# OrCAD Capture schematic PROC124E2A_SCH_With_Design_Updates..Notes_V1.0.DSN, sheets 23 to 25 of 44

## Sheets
23 21. BRD ID EEPROM &TEMP SENSORS: size C; title: BOARD ID EEPROM & TEMPERATURE SENSORS
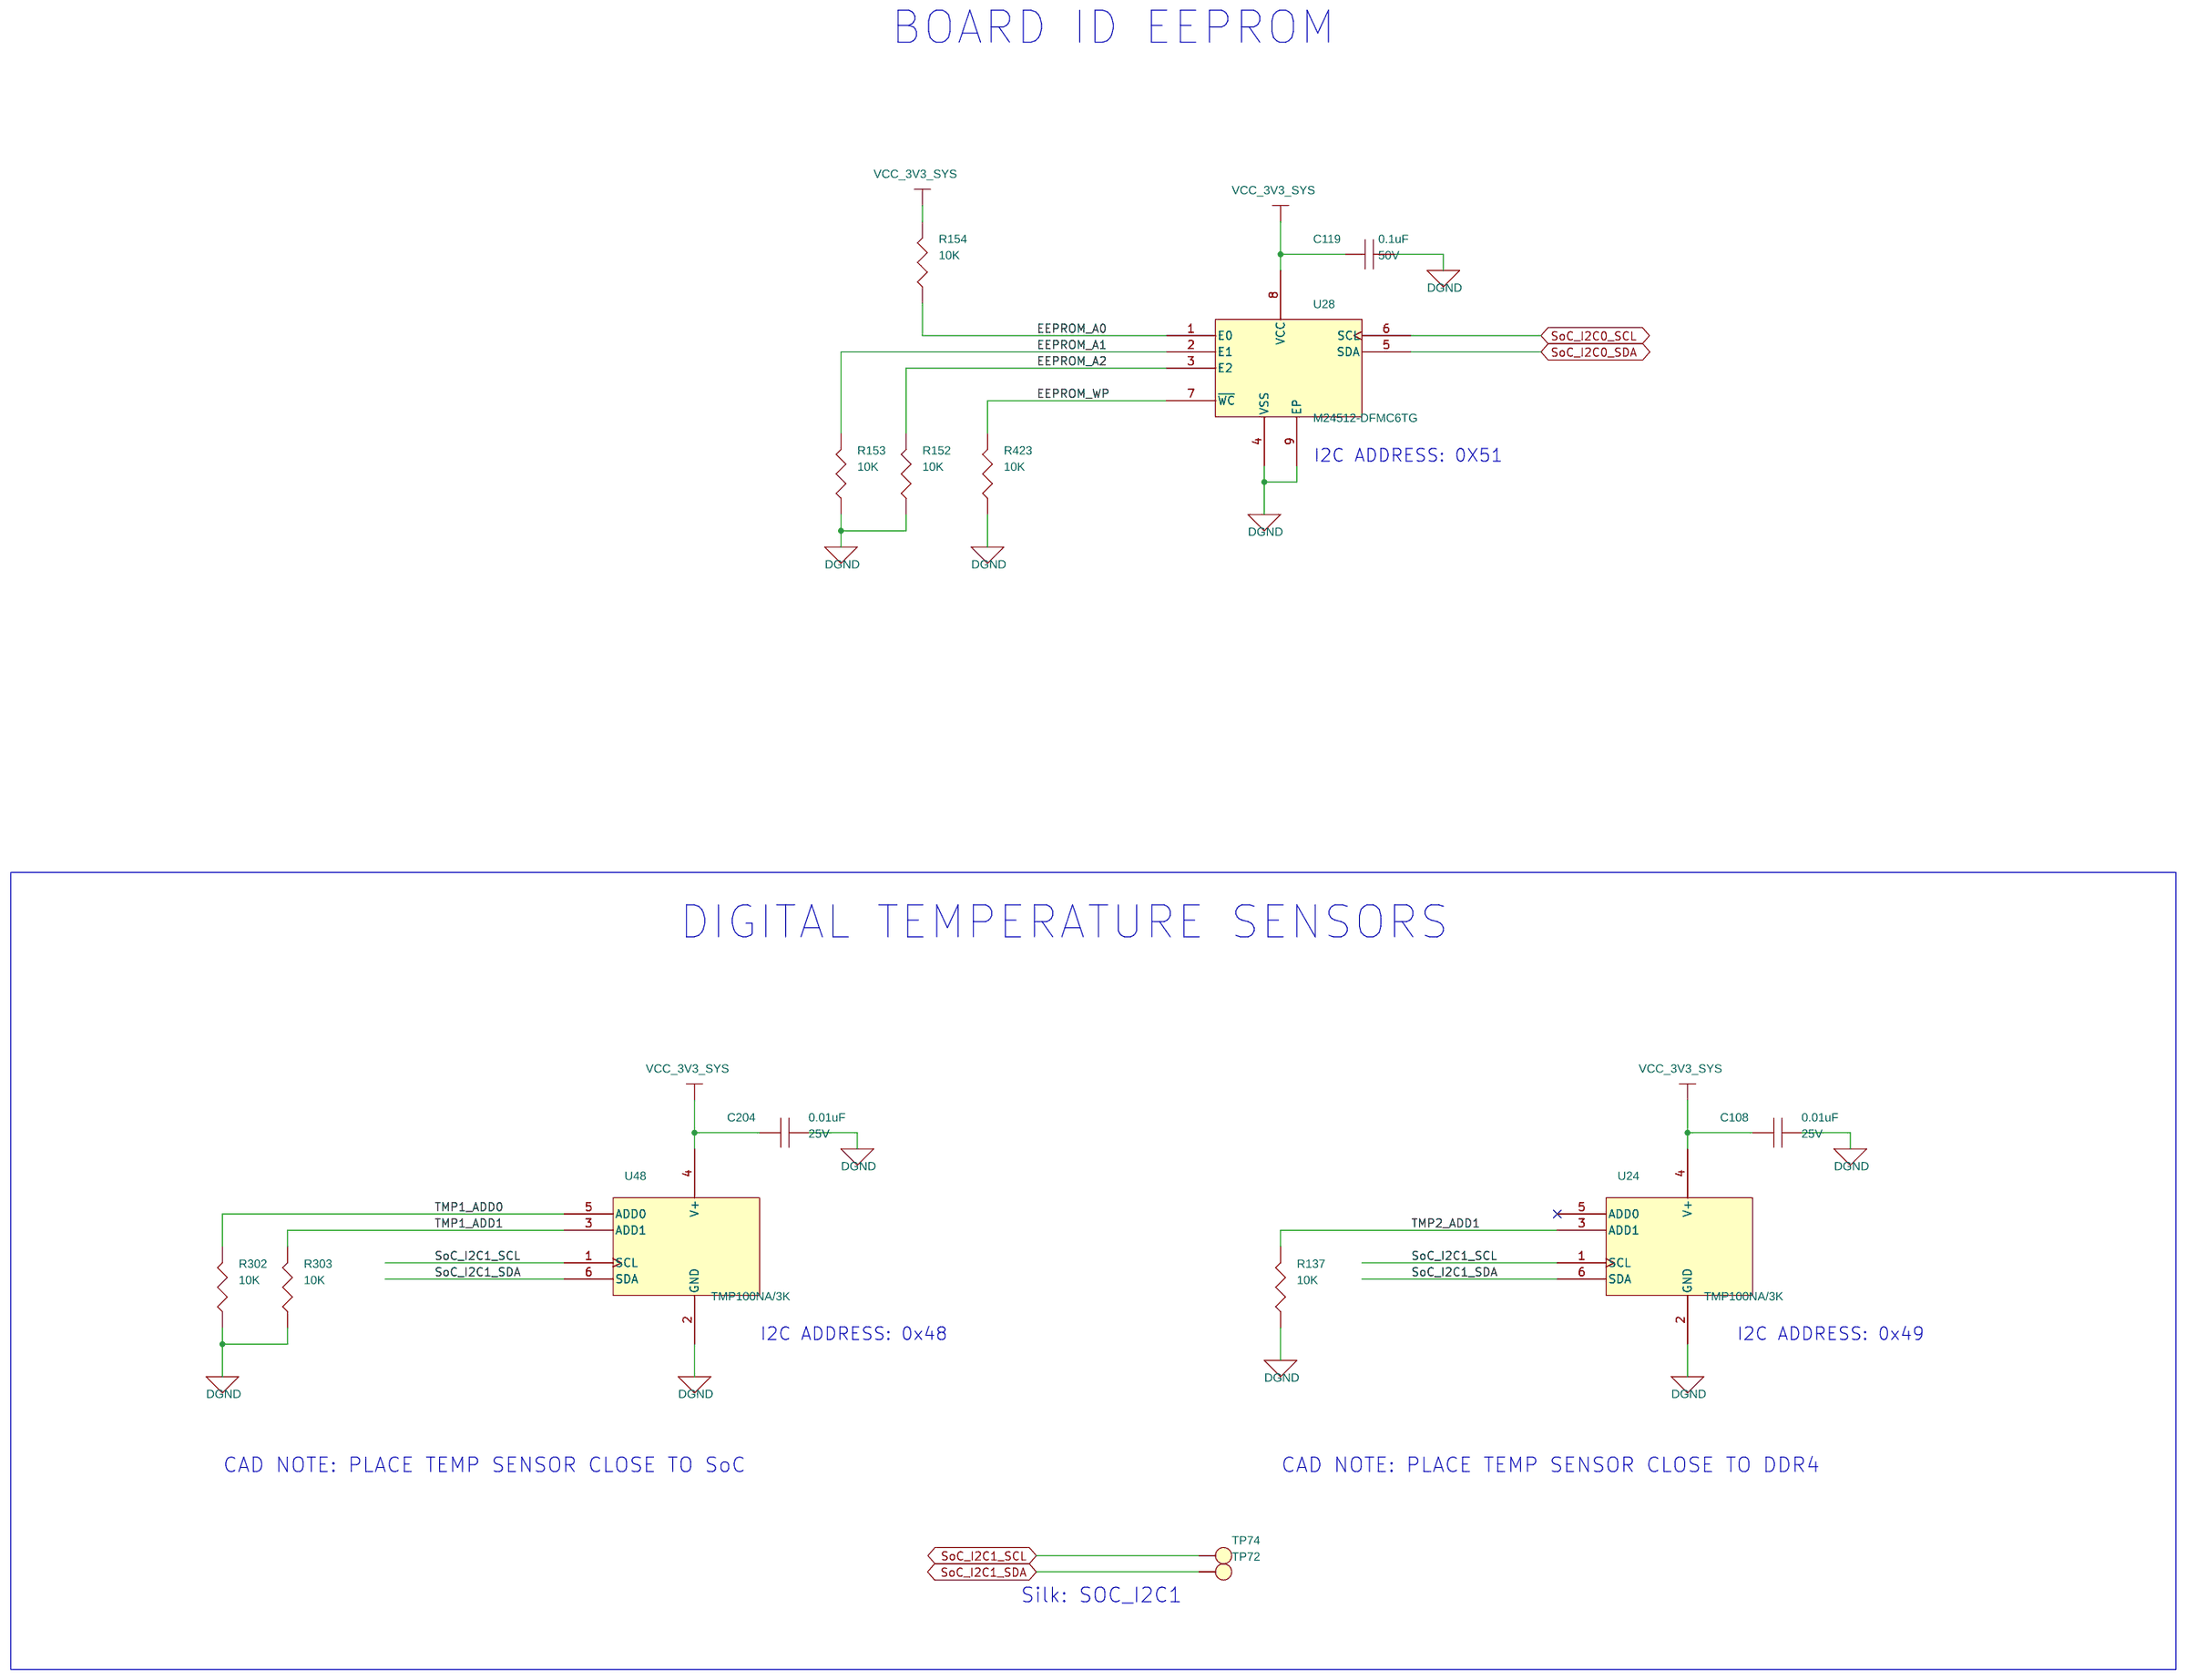
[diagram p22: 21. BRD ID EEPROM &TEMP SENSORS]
24 22. CPSW RGMII_1 ETHERNET PHY: size C
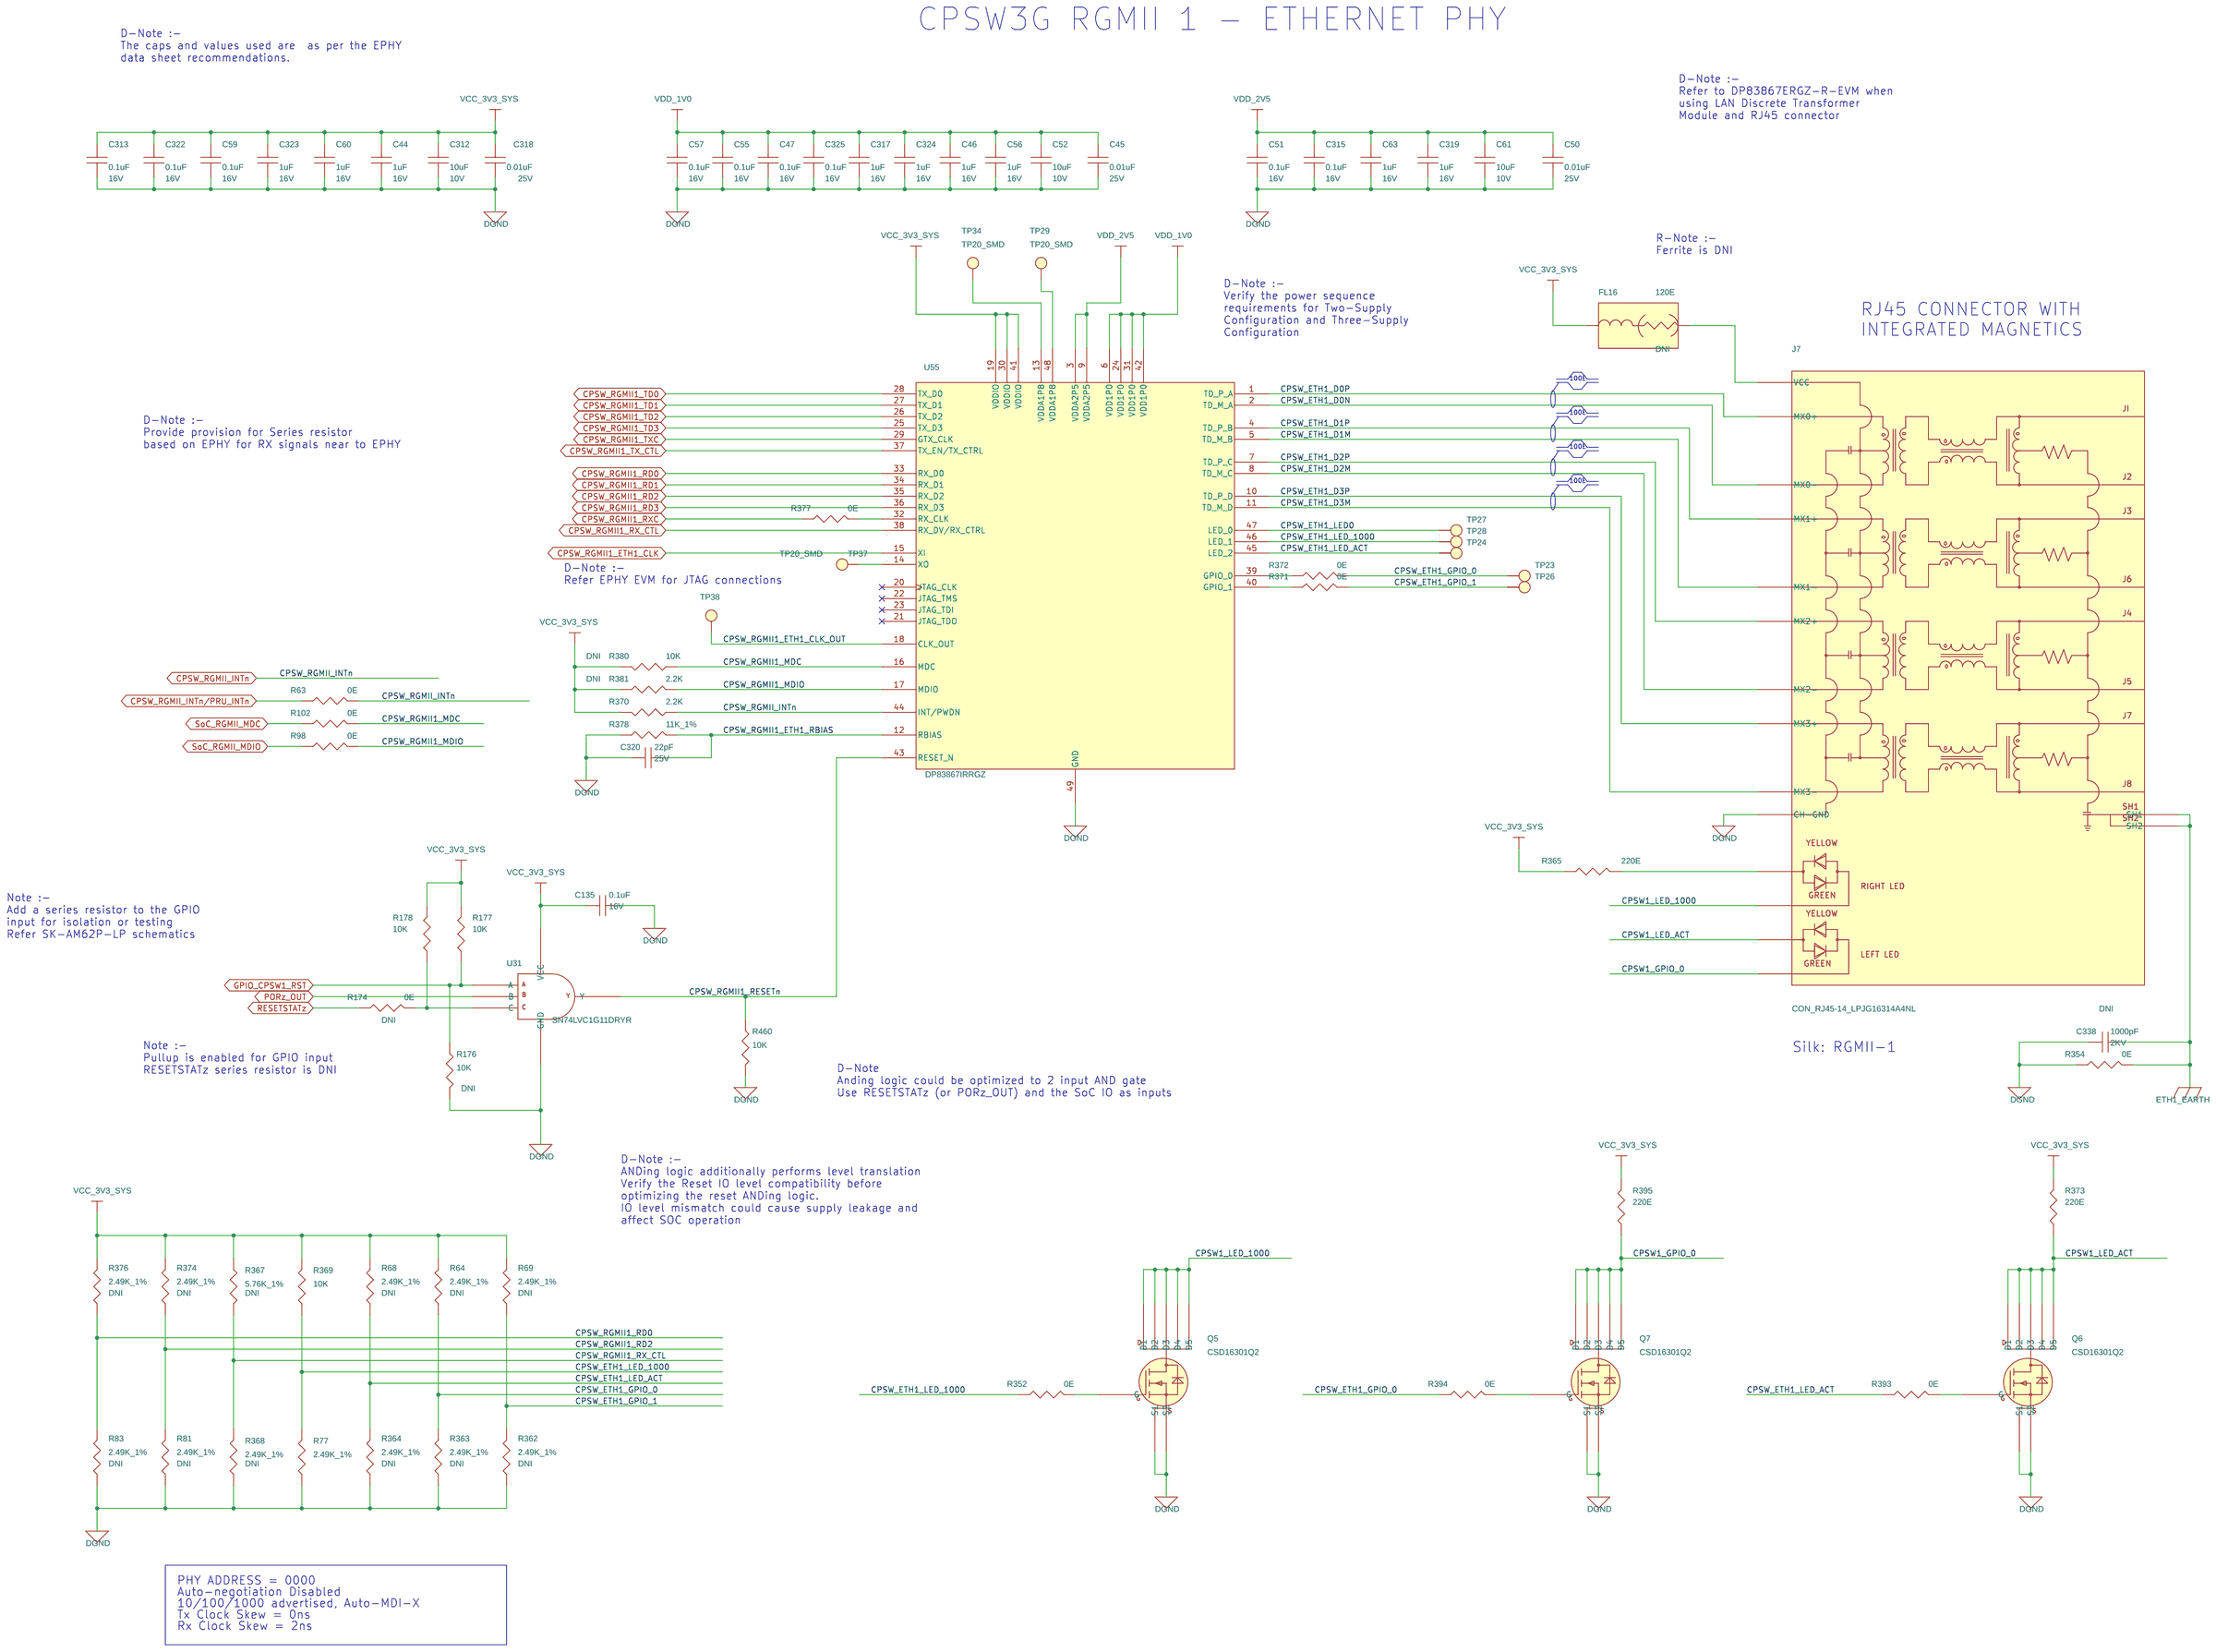
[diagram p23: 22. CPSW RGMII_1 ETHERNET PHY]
25 24. PHY CLK & LED DRIVER: size C; title: ETHERNET PHY CLOCK BUFFER & LED DRIVER
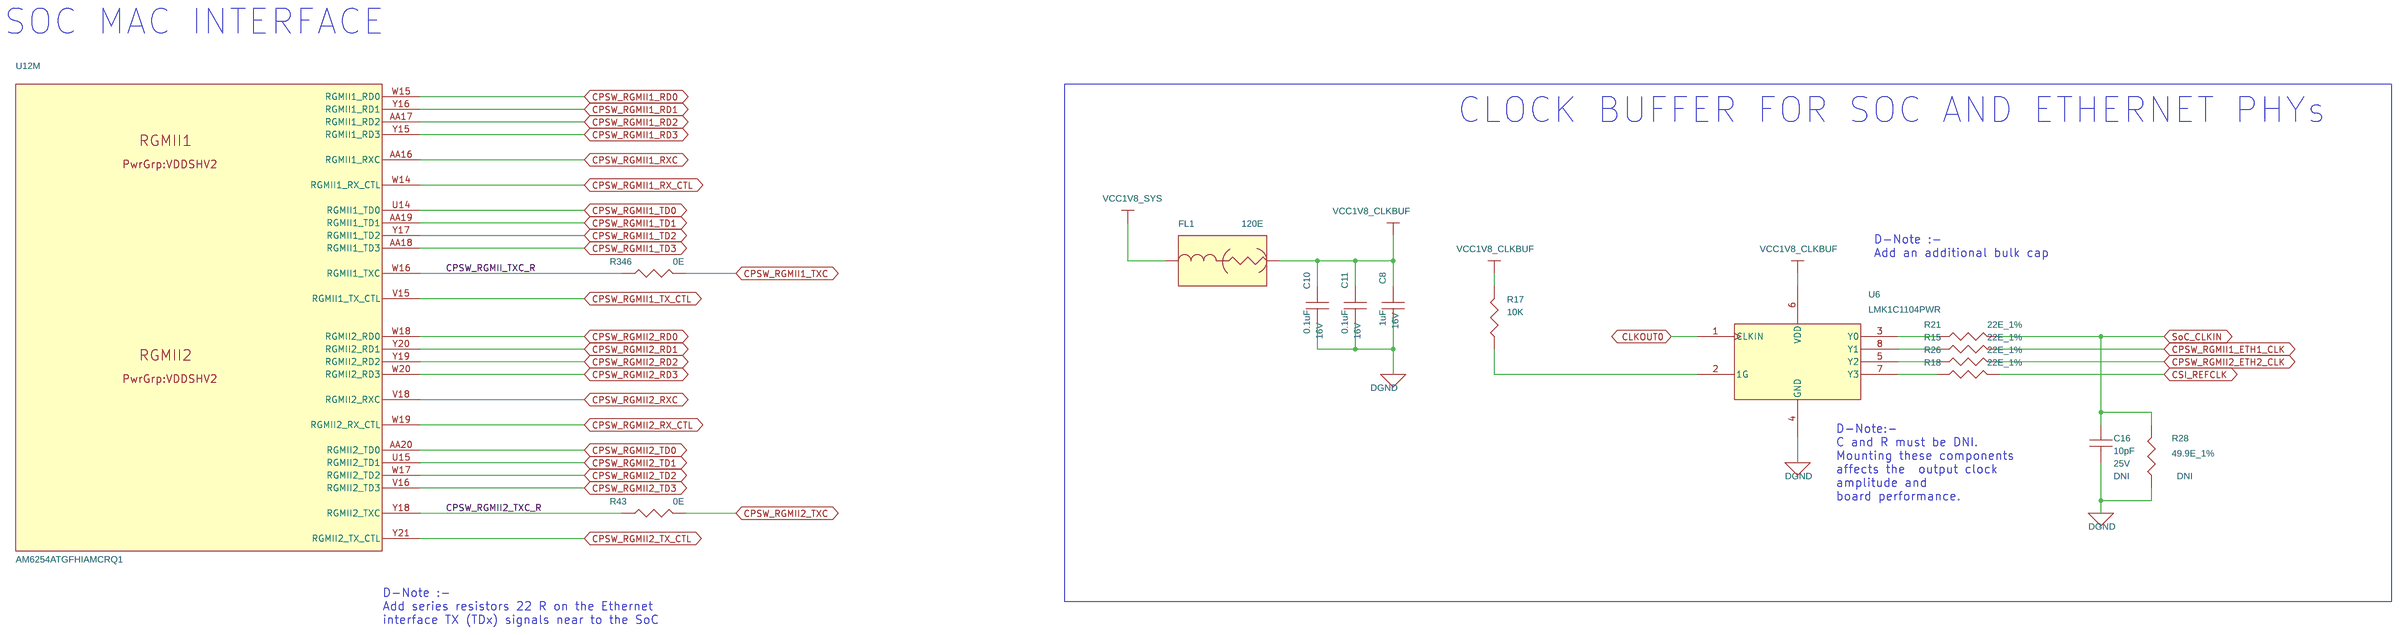
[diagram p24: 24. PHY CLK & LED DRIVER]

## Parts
sheet 15. SOC POWER CAPS
U12  AM6254ATGFHIAMCRQ1  [FCBGA441_31-49_680X680_2-6]  (sections A,B,C,D,E,F,G,H,I,J,K,L,M,N,O,P,Q,R)
sheet 21. BRD ID EEPROM &TEMP SENSORS
C108  0.01uF  [CAP0201_0-5]
C119  0.1uF  [CAP0402_0-75]
C204  0.01uF  [CAP0201_0-5]
R137  10K  [RES0201_0-5]
R152  10K  [RES0201_0-5]
R153  10K  [RES0201_0-5]
R154  10K  [RES0201_0-5]
R302  10K  [RES0201_0-5]
R303  10K  [RES0201_0-5]
R423  10K  [RES0201_0-5]
TP72  TP20_SMD  [TP20_SMD]
TP74  TP20_SMD  [TP20_SMD]
U24  TMP100NA/3K  [SOT23-6_1-5]
U28  M24512-DFMC6TG  [UFDFPN8_M24512_120X80_0-6]
U48  TMP100NA/3K  [SOT23-6_1-5]
sheet 22. CPSW RGMII_1 ETHERNET PHY
C44  1uF  [CAP0201_0-5]
C45  0.01uF  [CAP0201_0-5]
C46  1uF  [CAP0201_0-5]
C47  0.1uF  [CAP0201_0-5]
C50  0.01uF  [CAP0201_0-5]
C51  0.1uF  [CAP0201_0-5]
C52  10uF  [CAP0402_0-75]
C55  0.1uF  [CAP0201_0-5]
C56  1uF  [CAP0201_0-5]
C57  0.1uF  [CAP0201_0-5]
C59  0.1uF  [CAP0201_0-5]
C60  1uF  [CAP0201_0-5]
C61  10uF  [CAP0402_0-75]
C63  1uF  [CAP0201_0-5]
C135  0.1uF  [CAP0201_0-5]
C312  10uF  [CAP0402_0-75]
C313  0.1uF  [CAP0201_0-5]
C315  0.1uF  [CAP0201_0-5]
C317  1uF  [CAP0201_0-5]
C318  0.01uF  [CAP0201_0-5]
C319  1uF  [CAP0201_0-5]
C320  22pF  [CAP0201_0-5]
C322  0.1uF  [CAP0201_0-5]
C323  1uF  [CAP0201_0-5]
C324  1uF  [CAP0201_0-5]
C325  0.1uF  [CAP0201_0-5]
C338  1000pF  [CAP1206_1-75]
FL16  120E  [EMIFIL_BLM15A_0402_0-6]
J7  CON_RJ45-14_LPJG16314A4NL  [CON_RJ45-14_LPJG16314A4NL_S_R_T_13-6]
Q5  CSD16301Q2  [WSON6_CSD13202Q2_80X80_0-8]
Q6  CSD16301Q2  [WSON6_CSD13202Q2_80X80_0-8]
Q7  CSD16301Q2  [WSON6_CSD13202Q2_80X80_0-8]
R63  0E  [RES0402_0-5]
R64  2.49K_1%  [RES0402_0-5]
R68  2.49K_1%  [RES0402_0-5]
R69  2.49K_1%  [RES0402_0-5]
R77  2.49K_1%  [RES0402_0-5]
R81  2.49K_1%  [RES0402_0-5]
R83  2.49K_1%  [RES0402_0-5]
R98  0E  [RES0402_0-5]
R102  0E  [RES0402_0-5]
R174  0E  [RES0201_0-5]
R176  10K  [RES0201_0-5]
R177  10K  [RES0201_0-5]
R178  10K  [RES0201_0-5]
R352  0E  [RES0201_0-5]
R354  0E  [RES0603_0-75]
R362  2.49K_1%  [RES0402_0-5]
R363  2.49K_1%  [RES0402_0-5]
R364  2.49K_1%  [RES0402_0-5]
R365  220E  [RES0402_0-5]
R367  5.76K_1%  [RES0402_0-5]
R368  2.49K_1%  [RES0402_0-5]
R369  10K  [RES0201_0-5]
R370  2.2K  [RES0201_0-5]
R371  0E  [RES0201_0-5]
R372  0E  [RES0201_0-5]
R373  220E  [RES0402_0-5]
R374  2.49K_1%  [RES0402_0-5]
R376  2.49K_1%  [RES0402_0-5]
R377  0E  [RES0402_0-5]
R378  11K_1%  [RES0402_0-5]
R380  10K  [RES0201_0-5]
R381  2.2K  [RES0201_0-5]
R393  0E  [RES0201_0-5]
R394  0E  [RES0201_0-5]
R395  220E  [RES0402_0-5]
R460  10K  [RES0201_0-5]
TP23  TP20_SMD  [TP20_SMD]
TP24  TP20_SMD  [TP20_SMD]
TP26  TP20_SMD  [TP20_SMD]
TP27  TP20_SMD  [TP20_SMD]
TP28  TP20_SMD  [TP20_SMD]
TP29  TP20_SMD  [TP20_SMD]
TP34  TP20_SMD  [TP20_SMD]
TP37  TP20_SMD  [TP20_SMD]
TP38  TP20_SMD  [TP20_SMD]
U31  SN74LVC1G11DRYR  [SON6_SN74LVC2G17_40X60_0-6]
U55  DP83867IRRGZ  [QFN48_19-68_280X280_1]
sheet 24. PHY CLK & LED DRIVER
C8  1uF  [CAP0201_0-5]
C10  0.1uF  [CAP0201_0-5]
C11  0.1uF  [CAP0201_0-5]
C16  10pF  [CAP0201_0-5]
FL1  120E  [EMIFIL_BLM15A_0402_0-6]
R15  22E_1%  [RES0201_0-5]
R17  10K  [RES0201_0-5]
R18  22E_1%  [RES0201_0-5]
R21  22E_1%  [RES0201_0-5]
R26  22E_1%  [RES0201_0-5]
R28  49.9E_1%  [RES0402_0-5]
R43  0E  [RES0201_0-5]
R346  0E  [RES0201_0-5]
U6  LMK1C1104PWR  [TSSOP8_25-59_125X180_1-2]

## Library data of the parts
U12 = AM6254ATGFHIAMCRQ1_FCBGA441: IC AM62Q SoC MICROPROCESSOR FCBGA441; Chkd/date: PRADEEP/180324; Crtd /date: TAMILARASU/180324; Custom_Duty: 15%; Customs_HS_Code: 85423100; Distributor_name: NA; Distributor_part_number: NA; Footprint Path: Y:\MIS_DATABASE\Library\ALTIUM_TOOL\PCB_FOOTPRINTS\Altium_Footprint_Lib.PcbLib; Height: 2.57MM; Library Path: Y:\MIS_DATABASE\Library\ALTIUM_TOOL\SCHEMATICS_PARTS\MS_MICROPROCESSOR_Library.schlib; Mfr_name: TEXAS INSTRUMENTS; Mistral Part No: 141224030001-R; Package: FCBGA441; Part_type: ICS\DIGITAL\MICROPROCESSOR; Project: TI_AM62Q_BRD; RoHS: NA; Temperature: NA; Tolerance: NA; Voltage: NA; Wattage: NA; Weight: NA; Datasheet: Y:\MIS_DATABASE\DATASHEETS\ICS\DIGITAL\MICROCONTROLLER\AM62Q-SoC.PDF
C45 C50 C108 C204 C318 = CAP: CAP CERAMIC 0.01uF 25V 10% X5R 0201; Chkd/date: MANIRAJA/230118; Crtd /date: MANIRAJA/230118; Custom_Duty: 15%; Customs_HS_Code: 85322990; Distributor_name: DIGIKEY; Distributor_part_number: GRM033R61E103KA12J-ND; Footprint Path: Y:\MIS_DATABASE\Library\ALTIUM_TOOL\PCB_FOOTPRINTS\Altium_Footprint_Lib.PcbLib; Height: 0.33MM; Library Path: Y:\MIS_DATABASE\Library\ALTIUM_TOOL\SCHEMATICS_PARTS\MS_DISCRETE_Library.schlib; Mfr_name: MURATA; Mfr_part_number: GRM033R61E103KA12J; Mistral Part No: 120018010007-R; Package: 0201; Part_type: CAPACITORS\CERAMIC; Project: TI_MAXIE_CPB; RoHS: RoHS; Temperature: -55°C+85°C; Tolerance: 10%; Voltage: 25V; Wattage: NA; Weight: 0.33mg; Datasheet: Y:\MIS_DATABASE\DATASHEETS\CAPACITORS\GRM033R61E103KA12.PDF
C119 = CAP: CAP CERAMIC 0.1uF 50V 10% X7R 0402; Alt_Mfr_name: YAGEO AMERICA; Alt_Mfr_part_number: CC0402KRX5R8BB104; Chkd/date: MANIRAJA/261020; Crtd /date: ALVY/211020; Custom_Duty: 15%; Customs_HS_Code: 85322990; Distributor_name: DIGIKEY; Distributor_part_number: 490-10700-1-ND; Footprint Path: Y:\MIS_DATABASE\Library\ALTIUM_TOOL\PCB_FOOTPRINTS\Altium_Footprint_Lib.PcbLib; Height: 0.55MM; Library Path: Y:\MIS_DATABASE\Library\ALTIUM_TOOL\SCHEMATICS_PARTS\MS_DISCRETE_Library.schlib; Mfr_name: MURATA; Mfr_part_number: GRM155R71H104KE14D; Mistral Part No: 120011100014-R; Package: 0402; Part_type: CAPACITORS\CERAMIC; Project: J7_CP; RoHS: RoHS; Temperature: -55°C+125°C; Tolerance: 10%; Voltage: 50V; Wattage: NA; Weight: 3.1mg; Datasheet: Y:\MIS_DATABASE\DATASHEETS\CAPACITORS\GRM155R71H104KE14.PDF
R17 R137 R152-R154 R177 R178 R302 R303 R369 R423 R460 = RESISTOR: RES 10K 1/20W 5% 0201; Chkd/date: MANIRAJA/050517; Crtd /date: MANIRAJA/050517; Custom_Duty: 15%; Customs_HS_Code: 85332119; Distributor_name: DIGIKEY; Distributor_part_number: 311-10KNCT-ND; Footprint Path: Y:\MIS_DATABASE\Library\ALTIUM_TOOL\PCB_FOOTPRINTS\Altium_Footprint_Lib.PcbLib; Height: 0.26MM; Library Path: Y:\MIS_DATABASE\Library\ALTIUM_TOOL\SCHEMATICS_PARTS\MS_DISCRETE_Library.schlib; Mfr_name: YAGEO AMERICA; Mfr_part_number: RC0201JR-0710KL; Mistral Part No: 110010070051-R; Package: 0201; Part_type: RESISTORS\FIXED; Project: GOLDEN-I LITE; RoHS: RoHS; Temperature: -55°C+125°C; Tolerance: 5%; Voltage: NA; Wattage: 1/20W; Weight: 0.17mg; Datasheet: Y:\MIS_DATABASE\DATASHEETS\RESISTORS\RCXXXXL-SER_MAR18.PDF
TP23 TP24 TP26-TP28 TP38 TP72 TP74 = TESTPOINT: TESTPOINT CIR 20 SMD; Chkd/date: SHREESHAIL/171006; Crtd /date: MAZHAR/171006; Custom_Duty: NA; Customs_HS_Code: NA; Distributor_name: NA; Distributor_part_number: NA; Footprint Path: Y:\MIS_DATABASE\Library\ALTIUM_TOOL\PCB_FOOTPRINTS\Altium_Footprint_Lib.PcbLib; Height: NA; Library Path: Y:\MIS_DATABASE\Library\ALTIUM_TOOL\SCHEMATICS_PARTS\MS_DISCRETE_Library.schlib; MECHANICAL 3D STEP FILE: NA; Mfr_name: LOCAL; Mistral Part No: NA; Package: SMD; Project: BT MODULE_CSRBC04; RoHS: NA; Temperature: NA; Tolerance: NA; Voltage: NA; Wattage: NA; Weight: NA; Datasheet: NA
U24 U48 = TMP100NA_3K_SOT23-6: IC TEMPERATURE SENSOR WITH I2C AND SMBUS INTERFACE SOT23-6; Chkd/date: MANIRAJA/290817; Crtd /date: MANIRAJA/290817; Custom_Duty: 15%; Customs_HS_Code: 85423100; Distributor_name: DIGIKEY; Distributor_part_number: 296-26833-1-ND; Height: 1.45MM; Library Ref: TMP100NA/3K_SOT23-6; Mfr_name: TEXAS INSTRUMENTS; Mistral Part No: 141017080030-R; Package: SOT23-6; Part_type: ICS\DIGITAL\PERIPHERAL; Project: TI_MAXIE_CPB; RoHS: RoHS; Temperature: -55°C+125°C; Tolerance: NA; Voltage: NA; Wattage: NA; Weight: 120mg; Datasheet: Y:\MIS_DATABASE\DATASHEETS\ICS\DIGITAL\PERIPHERAL\TMP10XX.PDF
U28 = M24512_UFDFPN8: IC 1.7-5.5V 512Kb I2C SERIAL EEPROM UFDFPN8; Chkd/date: ALVY/240322; Crtd /date: ALVY/240322; Custom_Duty: 15%; Customs_HS_Code: 85423100; Distributor_name: DIGIKEY; Distributor_part_number: 497-15745-1-ND; Footprint Path: Y:\MIS_DATABASE\Library\ALTIUM_TOOL\PCB_FOOTPRINTS\Altium_Footprint_Lib.PcbLib; Height: 0.60MM; Library Path: Y:\MIS_DATABASE\Library\ALTIUM_TOOL\SCHEMATICS_PARTS\MS_MISCMEMORY_Library.schlib; Mfr_name: ST MICROELECTRONICS; Mistral Part No: 141122030005-R; Package: UFDFPN8; Part_type: ICS\DIGITAL\MEMORY; Project: TI_SK-AM62Q-LP EVM_BRD; RoHS: RoHS; Temperature: -40°C+85°C; Tolerance: NA; Voltage: NA; Wattage: NA; Weight: 16mg; Datasheet: Y:\MIS_DATABASE\DATASHEETS\ICS\MEMORY\M24512-W-R-DF.PDF
C8 C44 C46 C56 C60 C63 C317 C319 C323 C324 = CAP: CAP CERAMIC 1uF 16V 20% X5R 0201; Chkd/date: MANIRAJA/300520; Crtd /date: ALVY/260520; Custom_Duty: 15%; Customs_HS_Code: 85322990; Distributor_name: DIGIKEY; Distributor_part_number: 490-18654-1-ND; Footprint Path: Y:\MIS_DATABASE\Library\ALTIUM_TOOL\PCB_FOOTPRINTS\Altium_Footprint_Lib.PcbLib; Height: 0.39MM; Library Path: Y:\MIS_DATABASE\Library\ALTIUM_TOOL\SCHEMATICS_PARTS\MS_DISCRETE_Library.schlib; Mfr_name: MURATA; Mfr_part_number: GRM033R61C105ME15D; Mistral Part No: 120018090038-R; Package: 0201; Part_type: CAPACITORS\CERAMIC; Project: QCS610_NANOSOM; RoHS: RoHS; Temperature: -55°C+85°C; Tolerance: 20%; Voltage: 16V; Wattage: NA; Weight: 0.33mg; Datasheet: Y:\MIS_DATABASE\DATASHEETS\CAPACITORS\GRM033R61C105ME15.PDF
C10 C11 C47 C51 C55 C57 C59 C135 C313 C315 C322 C325 = CAP: CAP CERAMIC 0.1uF 16V 10% X5R 0201; Alt_Mfr_name: YAGEO AMERICA; Alt_Mfr_part_number: CC0402KRX5R8BB104; Chkd/date: MANIRAJA/230118; Crtd /date: MANIRAJA/230118; Custom_Duty: 15%; Customs_HS_Code: 85322990; Distributor_name: DIGIKEY; Distributor_part_number: 490-14305-1-ND; Footprint Path: Y:\MIS_DATABASE\Library\ALTIUM_TOOL\PCB_FOOTPRINTS\Altium_Footprint_Lib.PcbLib; Height: 0.33MM; Library Path: Y:\MIS_DATABASE\Library\ALTIUM_TOOL\SCHEMATICS_PARTS\MS_DISCRETE_Library.schlib; Mfr_name: MURATA; Mfr_part_number: GRM033R61C104KE14D; Mistral Part No: 120009030072-R; Package: 0201; Part_type: CAPACITORS\CERAMIC; Project: TI_MAXIE_CPB; RoHS: RoHS; Temperature: -55°C+85°C; Tolerance: 10%; Voltage: 16V; Wattage: NA; Weight: 0.33mg; Datasheet: Y:\MIS_DATABASE\DATASHEETS\CAPACITORS\GRM033R61C104KE14.PDF
C52 C61 C312 = CAP: CAP CERAMIC 10uF 10V 20% X5R 0402; Chkd/date: MANIRAJA/300520; Crtd /date: ALVY/260520; Custom_Duty: 15%; Customs_HS_Code: 85322990; Distributor_name: DIGIKEY; Distributor_part_number: 490-GRM155R61A106ME11DTR-ND; Footprint Path: Y:\MIS_DATABASE\Library\ALTIUM_TOOL\PCB_FOOTPRINTS\Altium_Footprint_Lib.PcbLib; Height: 0.55MM; Library Path: Y:\MIS_DATABASE\Library\ALTIUM_TOOL\SCHEMATICS_PARTS\MS_DISCRETE_Library.schlib; Mfr_name: MURATA; Mfr_part_number: GRM155R61A106ME11D; Mistral Part No: 120013110019-R; Package: 0402; Part_type: CAPACITORS\CERAMIC; Project: QCS610_NANOSOM; RoHS: RoHS; Temperature: -55°C+85°C; Tolerance: 20%; Voltage: 10V; Wattage: NA; Weight: 3.1mg; Datasheet: Y:\MIS_DATABASE\DATASHEETS\CAPACITORS\MURATA-GXX-SER_NOV17.PDF
C320 = CAP: CAP CERAMIC 22pF 25V 1% C0G(NP0) 0201; Chkd/date: MANIRAJA/270721; Crtd /date: ALVY/260721; Custom_Duty: 15%; Customs_HS_Code: 85322990; Distributor_name: DIGIKEY; Distributor_part_number: 490-14545-1-ND; Footprint Path: Y:\MIS_DATABASE\Library\ALTIUM_TOOL\PCB_FOOTPRINTS\Altium_Footprint_Lib.PcbLib; Height: 0.33MM; Library Path: Y:\MIS_DATABASE\Library\ALTIUM_TOOL\SCHEMATICS_PARTS\MS_DISCRETE_Library.schlib; Mfr_name: MURATA; Mfr_part_number: GRM0335C1E220FA01D; Mistral Part No: 120021070019-R; Package: 0201; Part_type: CAPACITORS\CERAMIC; Project: TI_AM335x SK_BRD; RoHS: RoHS; Temperature: -55°C+125°C; Tolerance: 1%; Voltage: 25V; Wattage: NA; Weight: 0.33mg; Datasheet: Y:\MIS_DATABASE\DATASHEETS\CAPACITORS\GRM0335C1E220FA01.PDF
C338 = CAP: CAP CERAMIC 1000pF 2KV 10% X7R 1206; Assembly_Instruction: DNI; Chkd/date: SHREESHAIL/291106; Crtd /date: MAZHAR/281106; Custom_Duty: 15%; Customs_HS_Code: 85322990; Distributor_name: DIGIKEY; Distributor_part_number: 478-2956-1-ND; Footprint Path: Y:\MIS_DATABASE\Library\ALTIUM_TOOL\PCB_FOOTPRINTS\Altium_Footprint_Lib.PcbLib; Height: 1.52MM; Library Path: Y:\MIS_DATABASE\Library\ALTIUM_TOOL\SCHEMATICS_PARTS\MS_DISCRETE_Library.schlib; Mfr_name: AVX CORPORATION; Mfr_part_number: 1206GC102KAT1A; Mistral Part No: 120015080006-R; Package: 1206; Part_type: CAPACITORS\CERAMIC; Project: ADR1B; RoHS: RoHS; Temperature: -55°C+125°C; Tolerance: 10%; Voltage: 2KV; Wattage: NA; Weight: 16.2mg; Datasheet: Y:\MIS_DATABASE\DATASHEETS\CAPACITORS\AVX_HV-MLC.PDF
FL16 = EMIFILTER_IND: IND FERRITE BEAD CHIP 120E 2A 0402; Assembly_Instruction: DNI; Chkd/date: NAVEED/241114; Crtd /date: USMAN/170613; Custom_Duty: 24%; Customs_HS_Code: 85369090; Distributor_name: DIGIKEY; Distributor_part_number: 490-9656-1-ND; Footprint Path: Y:\MIS_DATABASE\Library\ALTIUM_TOOL\PCB_FOOTPRINTS\Altium_Footprint_Lib.PcbLib; Height: 0.55MM; Library Path: Y:\MIS_DATABASE\Library\ALTIUM_TOOL\SCHEMATICS_PARTS\MS_FILTER_Library.schlib; Mfr_name: MURATA; Mfr_part_number: BLM15PX121SN1D; Mistral Part No: 130013060022-R; Package: 0402; Part_type: INDUCTOR; Project: GEN_3-8; RoHS: RoHS; Temperature: -55°C+125°C; Tolerance: 25%; Voltage: NA; Wattage: NA; Weight: 1mg; Datasheet: Y:\MIS_DATABASE\DATASHEETS\DISCRETES\INDUCTORS\BLM15-SN1-SER.PDF
J7 = CON_RJ45-14_LPJG16314A4NL: CON RJ-45 FEMALE 14POS RT TH; Chkd/date: VASANTHA/150714; Crtd /date: BALACHANDAR/120614; Custom_Duty: 24%; Customs_HS_Code: 85369090; Distributor_name: NA; Distributor_part_number: NA; Footprint Path: Y:\MIS_DATABASE\Library\ALTIUM_TOOL\PCB_FOOTPRINTS\Altium_Footprint_Lib.PcbLib; Height: 13.60MM; Library Path: Y:\MIS_DATABASE\Library\ALTIUM_TOOL\SCHEMATICS_PARTS\MS_CONNECTOR_Library.schlib; Mfr_name: LINK-PP; Mfr_part_number: LPJG16314A4NL; Mistral Part No: 150014060029-R; Package: THRU-HOLE; Part_type: CONNECTOR\JACK; Project: AEGIS; RoHS: RoHS; Temperature: -0°C+70°C; Tolerance: NA; Voltage: NA; Wattage: NA; Weight: NA; Datasheet: Y:\MIS_DATABASE\DATASHEETS\CONNECTORS\LPJG16314A4NL.PDF
Q5-Q7 = MOSFET_CSD17313Q2: IC MOSFET N-CHANNEL NEXFET 25V WSON6; Chkd/date: ALVY/071220; Crtd /date: MANIRAJA/071220; Custom_Duty: 15%; Customs_HS_Code: 85423100; Distributor_name: DIGIKEY; Distributor_part_number: 296-25260-1-ND; Footprint Path: Y:\MIS_DATABASE\Library\ALTIUM_TOOL\PCB_FOOTPRINTS\Altium_Footprint_Lib.PcbLib; Height: 0.80MM; Library Path: Y:\MIS_DATABASE\Library\ALTIUM_TOOL\SCHEMATICS_PARTS\MS_MOSFET_Library.schlib; Manufacturer: TEXAS INSTRUMENTS; Mfr_name: TEXAS INSTRUMENTS; Mistral Part No: 142020120008-R; Package: WSON6; Part_type: ICS\POWER\MOSFET; Project: TI_AM243x LP EVM; RoHS: RoHS; Temperature: -55°C+150°C; Tolerance: NA; Voltage: NA; Wattage: NA; Weight: 8.7mg; Datasheet: Y:\MIS_DATABASE\DATASHEETS\ICS\POWER\CSD16301Q2.PDF
R63 R98 R102 = RESISTOR: RES 0E 1/16W JUMPER 0402; Chkd/date: VASANTHA/201216; Crtd /date: MUDDU/190810; Custom_Duty: 15%; Customs_HS_Code: 85332119; Distributor_name: DIGIKEY; Distributor_part_number: 541-0.0JCT-ND; Footprint Path: Y:\MIS_DATABASE\Library\ALTIUM_TOOL\PCB_FOOTPRINTS\Altium_Footprint_Lib.PcbLib; Height: 0.40MM; Library Path: Y:\MIS_DATABASE\Library\ALTIUM_TOOL\SCHEMATICS_PARTS\MS_DISCRETE_Library.schlib; Mfr_name: VISHAY; Mfr_part_number: CRCW04020000Z0ED; Mistral Part No: 110010080019-R; Package: 0402; Part_type: RESISTORS\FIXED; Project: PB_BUGBASE; RoHS: RoHS; Temperature: -55°C+155°C; Tolerance: NA; Voltage: NA; Wattage: 1/16W; Weight: 0.65mg; Datasheet: Y:\MIS_DATABASE\DATASHEETS\RESISTORS\CRCW0603.PDF
R64 R68 R69 R81 R83 R362-R364 R368 R374 R376 = RESISTOR: RES 2.49K 1/16W 1% 0402; Assembly_Instruction: DNI; Chkd/date: VASANTHA/270516; Crtd /date: VASANTHA/270516; Custom_Duty: 15%; Customs_HS_Code: 85332119; Distributor_name: DIGIKEY; Distributor_part_number: 311-2.49KLRCT-ND; Footprint Path: Y:\MIS_DATABASE\Library\ALTIUM_TOOL\PCB_FOOTPRINTS\Altium_Footprint_Lib.PcbLib; Height: 0.40MM; Library Path: Y:\MIS_DATABASE\Library\ALTIUM_TOOL\SCHEMATICS_PARTS\MS_DISCRETE_Library.schlib; Mfr_name: YAGEO AMERICA; Mfr_part_number: RC0402FR-072K49L; Mistral Part No: 110016050020-R; Package: 0402; Part_type: RESISTORS\FIXED; Project: TMDXCSKCC; RoHS: RoHS; Temperature: -55°C+155°C; Tolerance: 1%; Voltage: NA; Wattage: 1/16W; Weight: 0.65mg; Datasheet: Y:\MIS_DATABASE\DATASHEETS\RESISTORS\RCXXXXL-SER_MAR18.PDF
R77 = RESISTOR: RES 2.49K 1/16W 1% 0402; Chkd/date: VASANTHA/270516; Crtd /date: VASANTHA/270516; Custom_Duty: 15%; Customs_HS_Code: 85332119; Distributor_name: DIGIKEY; Distributor_part_number: 311-2.49KLRCT-ND; Footprint Path: Y:\MIS_DATABASE\Library\ALTIUM_TOOL\PCB_FOOTPRINTS\Altium_Footprint_Lib.PcbLib; Height: 0.40MM; Library Path: Y:\MIS_DATABASE\Library\ALTIUM_TOOL\SCHEMATICS_PARTS\MS_DISCRETE_Library.schlib; Mfr_name: YAGEO AMERICA; Mfr_part_number: RC0402FR-072K49L; Mistral Part No: 110016050020-R; Package: 0402; Part_type: RESISTORS\FIXED; Project: TMDXCSKCC; RoHS: RoHS; Temperature: -55°C+155°C; Tolerance: 1%; Voltage: NA; Wattage: 1/16W; Weight: 0.65mg; Datasheet: Y:\MIS_DATABASE\DATASHEETS\RESISTORS\RCXXXXL-SER_MAR18.PDF
R174 = RESISTOR: RES 0E 1/20W 5% 0201; Assembly_Instruction: DNI; Chkd/date: NAVEED/301214; Crtd /date: MUDDU/120710; Custom_Duty: 15%; Customs_HS_Code: 85332119; Distributor_name: DIGIKEY; Distributor_part_number: 311-0.0NCT-ND; Footprint Path: Y:\MIS_DATABASE\Library\ALTIUM_TOOL\PCB_FOOTPRINTS\Altium_Footprint_Lib.PcbLib; Height: 0.26MM; Library Path: Y:\MIS_DATABASE\Library\ALTIUM_TOOL\SCHEMATICS_PARTS\MS_DISCRETE_Library.schlib; Mfr_name: YAGEO AMERICA; Mfr_part_number: RC0201JR-070RL; Mistral Part No: 110010070067-R; Package: 0201; Part_type: RESISTORS\FIXED; Project: PB_BUGBASE; RoHS: RoHS; Temperature: -55°C+125°C; Tolerance: 5%; Voltage: NA; Wattage: 1/20W; Weight: 0.17mg; Datasheet: Y:\MIS_DATABASE\DATASHEETS\RESISTORS\RCXXXXL-SER_MAR18.PDF
R176 R380 = RESISTOR: RES 10K 1/20W 5% 0201; Assembly_Instruction: DNI; Chkd/date: MANIRAJA/050517; Crtd /date: MANIRAJA/050517; Custom_Duty: 15%; Customs_HS_Code: 85332119; Distributor_name: DIGIKEY; Distributor_part_number: 311-10KNCT-ND; Footprint Path: Y:\MIS_DATABASE\Library\ALTIUM_TOOL\PCB_FOOTPRINTS\Altium_Footprint_Lib.PcbLib; Height: 0.26MM; Library Path: Y:\MIS_DATABASE\Library\ALTIUM_TOOL\SCHEMATICS_PARTS\MS_DISCRETE_Library.schlib; Mfr_name: YAGEO AMERICA; Mfr_part_number: RC0201JR-0710KL; Mistral Part No: 110010070051-R; Package: 0201; Part_type: RESISTORS\FIXED; Project: GOLDEN-I LITE; RoHS: RoHS; Temperature: -55°C+125°C; Tolerance: 5%; Voltage: NA; Wattage: 1/20W; Weight: 0.17mg; Datasheet: Y:\MIS_DATABASE\DATASHEETS\RESISTORS\RCXXXXL-SER_MAR18.PDF
R352 R371 R372 R393 R394 = RESISTOR: RES 0E 1/20W 5% 0201; Chkd/date: NAVEED/301214; Crtd /date: MUDDU/120710; Custom_Duty: 15%; Customs_HS_Code: 85332119; Distributor_name: DIGIKEY; Distributor_part_number: 311-0.0NCT-ND; Footprint Path: Y:\MIS_DATABASE\Library\ALTIUM_TOOL\PCB_FOOTPRINTS\Altium_Footprint_Lib.PcbLib; Height: 0.26MM; Library Path: Y:\MIS_DATABASE\Library\ALTIUM_TOOL\SCHEMATICS_PARTS\MS_DISCRETE_Library.schlib; Mfr_name: YAGEO AMERICA; Mfr_part_number: RC0201JR-070RL; Mistral Part No: 110010070067-R; Package: 0201; Part_type: RESISTORS\FIXED; Project: PB_BUGBASE; RoHS: RoHS; Temperature: -55°C+125°C; Tolerance: 5%; Voltage: NA; Wattage: 1/20W; Weight: 0.17mg; Datasheet: Y:\MIS_DATABASE\DATASHEETS\RESISTORS\RCXXXXL-SER_MAR18.PDF
R354 = RESISTOR: RES 0E 1/10W 5% 0603; Chkd/date: MANIRAJA/051217; Crtd /date: BAVISH/180211; Custom_Duty: 15%; Customs_HS_Code: 85332119; Distributor_name: DIGIKEY; Distributor_part_number: 311-0.0GRCT-ND; Footprint Path: Y:\MIS_DATABASE\Library\ALTIUM_TOOL\PCB_FOOTPRINTS\Altium_Footprint_Lib.PcbLib; Height: 0.55MM; Library Path: Y:\MIS_DATABASE\Library\ALTIUM_TOOL\SCHEMATICS_PARTS\MS_DISCRETE_Library.schlib; Mfr_name: YAGEO AMERICA; Mfr_part_number: RC0603JR-070RL; Mistral Part No: 110011020013-R; Package: 0603; Part_type: RESISTORS\FIXED; Project: KENNEL; RoHS: RoHS; Temperature: -55°C+155°C; Tolerance: 5%; Voltage: NA; Wattage: 1/10W; Weight: 2mg; Datasheet: Y:\MIS_DATABASE\DATASHEETS\RESISTORS\RCXXXXL-SER_MAR18.PDF
R365 R373 R395 = RESISTOR: RES 220E 1/10W 5% 0402; Chkd/date: VASANTHA/291216; Crtd /date: GEETHA/260406; Custom_Duty: 15%; Customs_HS_Code: 85332119; Distributor_name: DIGIKEY; Distributor_part_number: P220JCT-ND; Footprint Path: Y:\MIS_DATABASE\Library\ALTIUM_TOOL\PCB_FOOTPRINTS\Altium_Footprint_Lib.PcbLib; Height: 0.40MM; Library Path: Y:\MIS_DATABASE\Library\ALTIUM_TOOL\SCHEMATICS_PARTS\MS_DISCRETE_Library.schlib; Mfr_name: PANASONIC-ECG; Mfr_part_number: ERJ-2GEJ221X; Mistral Part No: 110009030506-R; Package: 0402; Part_type: RESISTORS\FIXED; Project: RED EYE; RoHS: RoHS; Temperature: -55°C+155°C; Tolerance: 5%; Voltage: NA; Wattage: 1/10W; Weight: 0.8mg; Datasheet: Y:\MIS_DATABASE\DATASHEETS\RESISTORS\PAN-ERJSER_NOV17.PDF
R367 = RESISTOR: RES 5.76K 1/10W 1% 0402; Assembly_Instruction: DNI; Chkd/date: MAZHAR/150709; Crtd /date: USMAN/220808; Custom_Duty: 15%; Customs_HS_Code: 85332119; Distributor_name: DIGIKEY; Distributor_part_number: P5.76KLCT-ND; Footprint Path: Y:\MIS_DATABASE\Library\ALTIUM_TOOL\PCB_FOOTPRINTS\Altium_Footprint_Lib.PcbLib; Height: 0.40MM; Library Path: Y:\MIS_DATABASE\Library\ALTIUM_TOOL\SCHEMATICS_PARTS\MS_DISCRETE_Library.schlib; Mfr_name: PANASONIC-ECG; Mfr_part_number: ERJ-2RKF5761X; Mistral Part No: 110009030945-R; Package: 0402; Part_type: RESISTORS\FIXED; Project: CPB; RoHS: RoHS; Temperature: -55°C+155°C; Tolerance: 1%; Voltage: NA; Wattage: 1/10W; Weight: 0.8mg; Datasheet: Y:\MIS_DATABASE\DATASHEETS\RESISTORS\PAN-ERJSER_NOV17.PDF
R370 = RESISTOR: RES 2.2K 1/20W 5% 0201; Chkd/date: MANIRAJA/310821; Crtd /date: ALVY/310821; Custom_Duty: 15%; Customs_HS_Code: 85332119; Distributor_name: DIGIKEY; Distributor_part_number: P123277CT-ND; Footprint Path: Y:\MIS_DATABASE\Library\ALTIUM_TOOL\PCB_FOOTPRINTS\Altium_Footprint_Lib.PcbLib; Height: 0.26MM; Library Path: Y:\MIS_DATABASE\Library\ALTIUM_TOOL\SCHEMATICS_PARTS\MS_DISCRETE_Library.schlib; Mfr_name: PANASONIC-ECG; Mfr_part_number: ERJ-1GNJ222C; Mistral Part No: 110009030427-R; Package: 0201; Part_type: RESISTORS\FIXED; Project: TI_AM335x SK_BRD; RoHS: RoHS; Temperature: -55°C+125°C; Tolerance: 5%; Voltage: NA; Wattage: 1/20W; Weight: 0.15mg; Datasheet: Y:\MIS_DATABASE\DATASHEETS\RESISTORS\PAN-ERJSER_NOV17.PDF
R377 = RESISTOR: RES 0E 1/16W JUMPER 0402; Chkd/date: VASANTHA/201216; Crtd /date: MUDDU/190810; Custom_Duty: 15%; Customs_HS_Code: 85332119; Distributor_name: DIGIKEY; Distributor_part_number: 541-0.0JCT-ND; Footprint Path: Y:\MIS_DATABASE\Library\ALTIUM_TOOL\PCB_FOOTPRINTS\Altium_Footprint_Lib.PcbLib; Height: 0.40MM; Library Path: Y:\MIS_DATABASE\Library\ALTIUM_TOOL\SCHEMATICS_PARTS\MS_DISCRETE_Library.schlib; Mfr_name: VISHAY; Mfr_part_number: CRCW04020000Z0ED; Mistral Part No: 110010080019-R; Package: 0402; Part_type: RESISTORS\FIXED; Project: PB_BUGBASE; RoHS: RoHS; SIGNAL_MODEL: RESISTOR_RES0402_0-5_0E_0E; Temperature: -55°C+155°C; Tolerance: NA; Voltage: NA; Wattage: 1/16W; Weight: 0.65mg; Datasheet: Y:\MIS_DATABASE\DATASHEETS\RESISTORS\CRCW0603.PDF
R378 = RESISTOR: RES 11K 1/16W 1% 0402; Chkd/date: VASANTHA/251115; Crtd /date: VASANTHA/251115; Custom_Duty: 15%; Customs_HS_Code: 85332119; Distributor_name: DIGIKEY; Distributor_part_number: 311-11.0KLRCT-ND; Footprint Path: Y:\MIS_DATABASE\Library\ALTIUM_TOOL\PCB_FOOTPRINTS\Altium_Footprint_Lib.PcbLib; Height: 0.40MM; Library Path: Y:\MIS_DATABASE\Library\ALTIUM_TOOL\SCHEMATICS_PARTS\MS_DISCRETE_Library.schlib; Mfr_name: YAGEO AMERICA; Mfr_part_number: RC0402FR-0711KL; Mistral Part No: 110015110012-R; Package: 0402; Part_type: RESISTORS\FIXED; Project: TI_VLAN_SWITCH; RoHS: RoHS; Temperature: -55°C+155°C; Tolerance: 1%; Voltage: NA; Wattage: 1/16W; Weight: 0.65mg; Datasheet: Y:\MIS_DATABASE\DATASHEETS\RESISTORS\RCXXXXL-SER_MAR18.PDF
R381 = RESISTOR: RES 2.2K 1/20W 5% 0201; Assembly_Instruction: DNI; Chkd/date: VASANTHA/010117; Crtd /date: MAZHAR/010605; Custom_Duty: 15%; Customs_HS_Code: 85332119; Distributor_name: DIGIKEY; Distributor_part_number: P2.2KAGCT-ND; Footprint Path: Y:\MIS_DATABASE\Library\ALTIUM_TOOL\PCB_FOOTPRINTS\Altium_Footprint_Lib.PcbLib; Height: 0.26MM; Library Path: Y:\MIS_DATABASE\Library\ALTIUM_TOOL\SCHEMATICS_PARTS\MS_DISCRETE_Library.schlib; Mfr_name: PANASONIC-ECG; Mfr_part_number: ERJ-1GEJ222C; Mistral Part No: 110009030427-R; Package: 0201; Part_type: RESISTORS\FIXED; Project: G4SLIM; RoHS: RoHS; Temperature: -55°C+125°C; Tolerance: 5%; Voltage: NA; Wattage: 1/20W; Weight: 0.15mg; Datasheet: Y:\MIS_DATABASE\DATASHEETS\RESISTORS\PAN-ERJXGE-FEB06.PDF
TP29 TP34 TP37 = TESTPOINT: TESTPOINT CIR 20 SMD; Chkd/date: SHREESHAIL/171006; Crtd /date: MAZHAR/171006; Custom_Duty: NA; Customs_HS_Code: NA; Distributor_name: NA; Distributor_part_number: NA; Footprint Path: Y:\MIS_DATABASE\Library\ALTIUM_TOOL\PCB_FOOTPRINTS\Altium_Footprint_Lib.PcbLib; Height: NA; Library Path: Y:\MIS_DATABASE\Library\ALTIUM_TOOL\SCHEMATICS_PARTS\MS_DISCRETE_Library.schlib; MECHANICAL 3D STEP FILE: NA; Manufacturer: LOCAL; Mfr_name: LOCAL; Mistral Part No: NA; Package: SMD; Project: BT MODULE_CSRBC04; RoHS: NA; Temperature: NA; Tolerance: NA; Voltage: NA; Wattage: NA; Weight: NA; Datasheet: NA
U31 = SN74LVC1G11DCKR_SC70-6: IC SINGLE 3-INPUT POSITIVE-AND GATE SON6; Chkd/date: MANIRAJA/270121; Crtd /date: ALVY/270121; Custom_Duty: 15%; Customs_HS_Code: 85423100; Distributor_name: DIGIKEY; Distributor_part_number: 296-30120-1-ND; Footprint Path: Y:\MIS_DATABASE\Library\ALTIUM_TOOL\PCB_FOOTPRINTS\Altium_Footprint_Lib.PcbLib; Height: 0.60MM; Library Path: Y:\MIS_DATABASE\Library\ALTIUM_TOOL\SCHEMATICS_PARTS\MS_GATE_Library.schlib; Mfr_name: TEXAS INSTRUMENTS; Mistral Part No: 141021010013-R; Package: SON6; Part_type: ICS\DIGITAL\GATES; Project: AM64X_SKEVM; RoHS: RoHS; Temperature: -40°C+125°C; Tolerance: NA; Voltage: NA; Wattage: NA; Weight: 33mg; Datasheet: Y:\MIS_DATABASE\DATASHEETS\ICS\DIGITAL\GATES\SN74LVC1G_NOV16.PDF
U55 = DP83867IRRGZ_VQFN48: IC HIGH IMMUNITY 10/100/1000 Mb/s ETHERNET PHY LAYER TRANSCEIVER VQFN48; Chkd/date: MANIRAJA/110817; Crtd /date: MANIRAJA/110817; Custom_Duty: 15%; Customs_HS_Code: 85423100; Distributor_name: DIGIKEY; Distributor_part_number: DP83867IRRGZT-ND; Height: 1.00MM; Mfr_name: TEXAS INSTRUMENTS; Mistral Part No: 143017080002-R; Package: VQFN48; Part_type: ICS\TELECOM\TRANSCEIVER; Project: TI_SVB_CONTROLLER CARD; RoHS: RoHS; Temperature: -40°C+85°C; Tolerance: NA; Voltage: NA; Wattage: NA; Weight: NA; Datasheet: Y:\MIS_DATABASE\DATASHEETS\ICS\DIGITAL\BUSTRANSCEIVER\DP83867I.PDF
C16 = CAP: CAP CERAMIC 10pF 25V 5% HI-Q C0G(NP0) 0201; Assembly_Instruction: DNI; Chkd/date: VASANTHA/081216; Crtd /date: MANIRAJA/081216; Custom_Duty: 15%; Customs_HS_Code: 85322990; Distributor_name: DIGIKEY; Distributor_part_number: 490-13312-1-ND; Footprint Path: Y:\MIS_DATABASE\Library\ALTIUM_TOOL\PCB_FOOTPRINTS\Altium_Footprint_Lib.PcbLib; Height: 0.33MM; Library Path: Y:\MIS_DATABASE\Library\ALTIUM_TOOL\SCHEMATICS_PARTS\MS_DISCRETE_Library.schlib; Mfr_name: MURATA; Mfr_part_number: GJM0335C1E100JB01D; Mistral Part No: 120016120010-R; Package: 0201; Part_type: CAPACITORS\CERAMIC; Project: OCTBTS5200; RoHS: RoHS; Temperature: -55°C+125°C; Tolerance: 5%; Voltage: 25V; Wattage: NA; Weight: 0.33mg; Datasheet: Y:\MIS_DATABASE\DATASHEETS\CAPACITORS\MURATA-GXX-SER_NOV17.PDF
FL1 = EMIFILTER_IND: IND FERRITE BEAD CHIP 120E 2A 0402; Chkd/date: NAVEED/241114; Crtd /date: USMAN/170613; Custom_Duty: 24%; Customs_HS_Code: 85369090; Distributor_name: DIGIKEY; Distributor_part_number: 490-9656-1-ND; Footprint Path: Y:\MIS_DATABASE\Library\ALTIUM_TOOL\PCB_FOOTPRINTS\Altium_Footprint_Lib.PcbLib; Height: 0.55MM; Library Path: Y:\MIS_DATABASE\Library\ALTIUM_TOOL\SCHEMATICS_PARTS\MS_FILTER_Library.schlib; Mfr_name: MURATA; Mfr_part_number: BLM15PX121SN1D; Mistral Part No: 130013060022-R; Package: 0402; Part_type: INDUCTOR; Project: GEN_3-8; RoHS: RoHS; Temperature: -55°C+125°C; Tolerance: 25%; Voltage: NA; Wattage: NA; Weight: 1mg; Datasheet: Y:\MIS_DATABASE\DATASHEETS\DISCRETES\INDUCTORS\BLM15-SN1-SER.PDF
R15 R18 R21 R26 = RESISTOR: RES 22E 1/20W 1% 0201; Chkd/date: PRAVEEN/080922; Crtd /date: TAMILARASU/080922; Custom_Duty: 15%; Customs_HS_Code: 85332119; Distributor_name: DIGIKEY; Distributor_part_number: P122843CT-ND; Footprint Path: Y:\MIS_DATABASE\Library\ALTIUM_TOOL\PCB_FOOTPRINTS\Altium_Footprint_Lib.PcbLib; Height: 0.26MM; Library Path: Y:\MIS_DATABASE\Library\ALTIUM_TOOL\SCHEMATICS_PARTS\MS_DISCRETE_Library.schlib; Mfr_name: PANASONIC-ECG; Mfr_part_number: ERJ-1GNF22R0C; Mistral Part No: 110022090007-R; Package: 0201; Part_type: RESISTORS\FIXED; Project: SK AM62Q LP EVM BRD; RoHS: RoHS; Temperature: -55°C+125°C; Tolerance: 1%; Voltage: NA; Wattage: 1/20W; Weight: 0.15mg; Datasheet: Y:\MIS_DATABASE\DATASHEETS\RESISTORS\PAN-ERJSER_NOV17.PDF
R28 = RESISTOR: RES 49.9E 1/16W 1% 0402; Assembly_Instruction: DNI; Chkd/date: MANIRAJA/210519; Crtd /date: MANIRAJA/210519; Custom_Duty: 15%; Customs_HS_Code: 85332119; Distributor_name: DIGIKEY; Distributor_part_number: 541-3967-1-ND; Footprint Path: Y:\MIS_DATABASE\Library\ALTIUM_TOOL\PCB_FOOTPRINTS\Altium_Footprint_Lib.PcbLib; Height: 0.35MM; Library Path: Y:\MIS_DATABASE\Library\ALTIUM_TOOL\SCHEMATICS_PARTS\MS_DISCRETE_Library.schlib; Mfr_name: VISHAY; Mfr_part_number: CRCW040249R9FKEDC; Mistral Part No: 110009030846-R; Package: 0402; Part_type: RESISTORS\FIXED; Project: RFSU_RFTJ_CARD; RoHS: RoHS; Temperature: -55°C+155°C; Tolerance: 1%; Voltage: NA; Wattage: 1/16W; Weight: 0.65mg; Datasheet: Y:\MIS_DATABASE\DATASHEETS\RESISTORS\CRCW_C-SER.PDF
R43 = RESISTOR: RES 0E 1/20W 5% 0201; Chkd/date: NAVEED/301214; Crtd /date: MUDDU/120710; Custom_Duty: 15%; Customs_HS_Code: 85332119; Distributor_name: DIGIKEY; Distributor_part_number: 311-0.0NCT-ND; Footprint Path: Y:\MIS_DATABASE\Library\ALTIUM_TOOL\PCB_FOOTPRINTS\Altium_Footprint_Lib.PcbLib; Height: 0.26MM; Library Path: Y:\MIS_DATABASE\Library\ALTIUM_TOOL\SCHEMATICS_PARTS\MS_DISCRETE_Library.schlib; Mfr_name: YAGEO AMERICA; Mfr_part_number: RC0201JR-070RL; Mistral Part No: 110010070067-R; Package: 0201; Part_type: RESISTORS\FIXED; Project: PB_BUGBASE; RoHS: RoHS; SIGNAL_MODEL: RESISTOR_RES0402_0-5_0E_0E; Temperature: -55°C+125°C; Tolerance: 5%; Voltage: NA; Wattage: 1/20W; Weight: 0.17mg; Datasheet: Y:\MIS_DATABASE\DATASHEETS\RESISTORS\RCXXXXL-SER_MAR18.PDF
R346 = RESISTOR: RES 0E 1/20W 5% 0201; Chkd/date: NAVEED/301214; Crtd /date: MUDDU/120710; Custom_Duty: 15%; Customs_HS_Code: 85332119; Distributor_name: DIGIKEY; Distributor_part_number: 311-0.0NCT-ND; Footprint Path: Y:\MIS_DATABASE\Library\ALTIUM_TOOL\PCB_FOOTPRINTS\Altium_Footprint_Lib.PcbLib; Height: 0.26MM; Library Path: Y:\MIS_DATABASE\Library\ALTIUM_TOOL\SCHEMATICS_PARTS\MS_DISCRETE_Library.schlib; Mfr_name: YAGEO AMERICA; Mfr_part_number: RC0201JR-070RL; Mistral Part No: 110010070067-R; Package: 0201; Part_type: RESISTORS\FIXED; Project: PB_BUGBASE; RoHS: RoHS; SIGNAL_MODEL: RESISTOR_RES0201_0-5_0E_0E; Temperature: -55°C+125°C; Tolerance: 5%; Voltage: NA; Wattage: 1/20W; Weight: 0.17mg; Datasheet: Y:\MIS_DATABASE\DATASHEETS\RESISTORS\RCXXXXL-SER_MAR18.PDF
U6 = LMK1C1104_TSSOP8: IC LVCMOS CLOCK BUFFER TSSOP8; Chkd/date: MANIRAJA/190520; Crtd /date: ALVY/190520; Custom_Duty: 15%; Customs_HS_Code: 85423100; Distributor_name: DIGIKEY; Distributor_part_number: 296-LMK1C1104PWRCT-ND; Footprint Path: Y:\MIS_DATABASE\Library\ALTIUM_TOOL\PCB_FOOTPRINTS\Altium_Footprint_Lib.PcbLib; Height: 1.20MM; Library Path: Y:\MIS_DATABASE\Library\ALTIUM_TOOL\SCHEMATICS_PARTS\MS_COMBINATIONAL_Library.schlib; Manufacturer: TEXAS INSTRUMENTS; Mfr_name: TEXAS INSTRUMENTS; Mistral Part No: 141020050011-R; Package: TSSOP8; Part_type: ICS\DIGITAL\COMBINATIONAL; Project: RETROFIT-RAD2; RoHS: RoHS; Temperature: -40°C+125°C; Tolerance: NA; Voltage: NA; Wattage: NA; Weight: 34.2mg; Datasheet: Y:\MIS_DATABASE\DATASHEETS\ICS\DIGITAL\COMBINATIONAL\LMK1C1104.PDF

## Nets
DGND: C8.1 C10.1 C11.1 C16.2 C44.2 C45.2 C46.2 C47.2 C50.2 C51.2 C52.2 C55.2 C56.2 C57.2 C59.2 C60.2 C61.2 C63.2 C108.1 C119.2 C135.2 C204.1 C312.2 C313.2 C315.2 C317.2 C318.2 C319.2 C320.1 C322.2 C323.2 C324.2 C325.2 C338.2 J7.1(CH-GND) Q5.4(S1) Q5.7(S2) Q6.4(S1) Q6.7(S2) Q7.4(S1) Q7.7(S2) R28.1 R77.1 R81.1 R83.1 R137.2 R152.2 R153.2 R176.2 R302.2 R303.2 R354.2 R362.1 R363.1 R364.1 R368.1 R378.2 R423.2 R460.2 U6.4(GND) U24.2(GND) U28.4(VSS) U28.9(EP) U31.2(GND) U48.2(GND) U55.49(GND) ; also on sheet 1 2 3 4 13 14 15 16 17 18 19 20 21 22 26 27 28 29 30 31 32 33 34 35 36 37 38 39 40 41 42 43
VCC1V8_CLKBUF: C8.2 C10.2 C11.2 FL1.2 R17.2 U6.6(VDD) ; also on sheet 42
VCC1V8_SYS: FL1.1 ; also on sheet 4 16 19 20 22 34 37 39 40 42
VCC_3V3_SYS: C44.1 C59.1 C60.1 C108.2 C119.1 C135.1 C204.2 C312.1 C313.1 C318.1 C322.1 C323.1 FL16.1 R64.2 R68.2 R69.2 R154.1 R177.2 R178.2 R365.1 R367.1 R369.2 R370.2 R373.2 R374.2 R376.2 R380.2 R381.1 R395.2 U24.4(V+) U28.8(VCC) U31.5(VCC) U48.4(V+) U55.19(VDDIO) U55.30(VDDIO) U55.41(VDDIO) ; also on sheet 1 4 15 16 19 20 21 26 27 29 30 31 32 33 34 36 37 38 39 40 41 42 43
VDD_1V0: C45.1 C46.1 C47.1 C52.1 C55.1 C56.1 C57.1 C317.1 C324.1 C325.1 U55.6(VDD1P0) U55.24(VDD1P0) U55.31(VDD1P0) U55.42(VDD1P0) ; also on sheet 1 15
VDD_2V5: C50.1 C51.1 C61.1 C63.1 C315.1 C319.1 U55.3(VDDA2P5) U55.9(VDDA2P5) ; also on sheet 1 15
CLKOUT0: U6.1(CLKIN) ; also on sheet 42
CPSW1_GPIO_0: J7.14 Q7.1(D1) Q7.2(D2) Q7.5(D3) Q7.6(D4) Q7.8(D5) R395.1
CPSW1_LED_1000: J7.12 Q5.1(D1) Q5.2(D2) Q5.5(D3) Q5.6(D4) Q5.8(D5)
CPSW1_LED_ACT: J7.13 Q6.1(D1) Q6.2(D2) Q6.5(D3) Q6.6(D4) Q6.8(D5) R373.1
CPSW_ETH1_D0N: J7.10(MX0-) U55.2(TD_M_A)
CPSW_ETH1_D0P: J7.9(MX0+) U55.1(TD_P_A)
CPSW_ETH1_D1M: J7.8(MX1-) U55.5(TD_M_B)
CPSW_ETH1_D1P: J7.7(MX1+) U55.4(TD_P_B)
CPSW_ETH1_D2M: J7.6(MX2-) U55.8(TD_M_C)
CPSW_ETH1_D2P: J7.5(MX2+) U55.7(TD_P_C)
CPSW_ETH1_D3M: J7.4(MX3-) U55.11(TD_M_D)
CPSW_ETH1_D3P: J7.3(MX3+) U55.10(TD_P_D)
CPSW_ETH1_GPIO_0: R64.1 R363.2 R372.1 R394.1 TP23.1(TP)
CPSW_ETH1_GPIO_1: R69.1 R362.2 R371.1 TP26.1(TP)
CPSW_ETH1_LED0: TP27.1(TP) U55.47(LED_0)
CPSW_ETH1_LED_1000: R77.2 R352.1 R369.1 TP28.1(TP) U55.46(LED_1)
CPSW_ETH1_LED_ACT: R68.1 R364.2 R393.1 TP24.1(TP) U55.45(LED_2)
CPSW_RGMII1_ETH1_CLK: R15.2 U55.15(XI)
CPSW_RGMII1_ETH1_CLK_OUT: TP38.1(TP) U55.18(CLK_OUT)
CPSW_RGMII1_ETH1_RBIAS: C320.2 R378.1 U55.12(RBIAS)
CPSW_RGMII1_MDC: R102.2 R380.1 U55.16(MDC)
CPSW_RGMII1_MDIO: R98.2 R381.2 U55.17(MDIO)
CPSW_RGMII1_RD0: R83.2 R376.1 U12.W15(RGMII1_RD0) U55.33(RX_D0)
CPSW_RGMII1_RD1: U12.Y16(RGMII1_RD1) U55.34(RX_D1)
CPSW_RGMII1_RD2: R81.2 R374.1 U12.AA17(RGMII1_RD2) U55.35(RX_D2)
CPSW_RGMII1_RD3: U12.Y15(RGMII1_RD3) U55.36(RX_D3)
CPSW_RGMII1_RESETn: R460.1 U31.4(Y) U55.43(RESET_N)
CPSW_RGMII1_RX_CTL: R367.2 R368.2 U12.W14(RGMII1_RX_CTL) U55.38(RX_DV/RX_CTRL)
CPSW_RGMII1_RXC: R377.1 U12.AA16(RGMII1_RXC)
CPSW_RGMII1_TD0: U12.U14(RGMII1_TD0) U55.28(TX_D0)
CPSW_RGMII1_TD1: U12.AA19(RGMII1_TD1) U55.27(TX_D1)
CPSW_RGMII1_TD2: U12.Y17(RGMII1_TD2) U55.26(TX_D2)
CPSW_RGMII1_TD3: U12.AA18(RGMII1_TD3) U55.25(TX_D3)
CPSW_RGMII1_TX_CTL: U12.V15(RGMII1_TX_CTL) U55.37(TX_EN/TX_CTRL)
CPSW_RGMII1_TXC: R346.2 U55.29(GTX_CLK)
CPSW_RGMII2_ETH2_CLK: R26.2 ; also on sheet 1
CPSW_RGMII2_RD0: U12.W18(RGMII2_RD0) ; also on sheet 1
CPSW_RGMII2_RD1: U12.Y20(RGMII2_RD1) ; also on sheet 1
CPSW_RGMII2_RD2: U12.Y19(RGMII2_RD2) ; also on sheet 1
CPSW_RGMII2_RD3: U12.W20(RGMII2_RD3) ; also on sheet 1
CPSW_RGMII2_RX_CTL: U12.W19(RGMII2_RX_CTL) ; also on sheet 1
CPSW_RGMII2_RXC: U12.V18(RGMII2_RXC) ; also on sheet 1
CPSW_RGMII2_TD0: U12.AA20(RGMII2_TD0) ; also on sheet 1
CPSW_RGMII2_TD1: U12.U15(RGMII2_TD1) ; also on sheet 1
CPSW_RGMII2_TD2: U12.W17(RGMII2_TD2) ; also on sheet 1
CPSW_RGMII2_TD3: U12.V16(RGMII2_TD3) ; also on sheet 1
CPSW_RGMII2_TX_CTL: U12.Y21(RGMII2_TX_CTL) ; also on sheet 1
CPSW_RGMII2_TXC: R43.2 ; also on sheet 1
CPSW_RGMII2_TXC_R: R43.1 U12.Y18(RGMII2_TXC)
CPSW_RGMII_INTn: R63.2 R370.1 U55.44(INT/PWDN) ; also on sheet 1
CPSW_RGMII_INTn/PRU_INTn: R63.1 ; also on sheet 32 42
CPSW_RGMII_TXC_R: R346.1 U12.W16(RGMII1_TXC)
CSI_REFCLK: R18.2 ; also on sheet 38
EEPROM_A0: R154.2 U28.1(E0)
EEPROM_A1: R153.1 U28.2(E1)
EEPROM_A2: R152.1 U28.3(E2)
EEPROM_WP: R423.1 U28.7(~{WC})
ETH1_EARTH: C338.1 J7.15(SH1) J7.16(SH2) R354.1
GPIO_CPSW1_RST: R176.1 R177.1 U31.1(A) ; also on sheet 39
PORz_OUT: U31.3(B) ; also on sheet 1 21 27 42
RESETSTATz: R174.1 ; also on sheet 1 4 20 21 22 27 32 37 38 39 40 41 42
SoC_CLKIN: C16.1 R21.2 R28.2 ; also on sheet 34
SoC_I2C0_SCL: U28.6(SCL) ; also on sheet 4 13 32 33 37 42
SoC_I2C0_SDA: U28.5(SDA) ; also on sheet 4 13 32 33 37 42
SOC_I2C1_SCL: TP74.1(TP) U24.1(SCL) U48.1(SCL) ; also on sheet 16 26 39 40 41 42
SOC_I2C1_SDA: TP72.1(TP) U24.6(SDA) U48.6(SDA) ; also on sheet 16 26 39 40 41 42
SoC_RGMII_MDC: R102.1 ; also on sheet 1 32
SoC_RGMII_MDIO: R98.1 ; also on sheet 1 32
TMP1_ADD0: R302.1 U48.5(ADD0)
TMP1_ADD1: R303.1 U48.3(ADD1)
TMP2_ADD1: R137.1 U24.3(ADD1)
N16943223: R17.1 U6.2(1G)
N17110597: TP34.1(TP) U55.13(VDDA1P8)
N17133547: FL16.2 J7.2(VCC)
N17137240: J7.11 R365.2
N17167245: R377.2 U55.32(RX_CLK)
N17269599: R174.2 R178.1 U31.6(C)
N17653582: Q5.3(G) R352.2
N17796705: Q6.3(G) R393.2
N17796716: Q7.3(G) R394.2
N18576337: R372.2 U55.39(GPIO_0)
N18576340: R371.2 U55.40(GPIO_1)
N20900570: R21.1 U6.3(Y0)
N20900572: R15.1 U6.8(Y1)
N20900574: R26.1 U6.5(Y2)
N20900809: R18.1 U6.7(Y3)
N21016640: TP29.1(TP) U55.48(VDDA1P8)
N21079949: TP37.1(TP) U55.14(XO)

Not connected (* = marked no-connect by the designer): U24 5(ADD0)*; U55 20(JTAG_CLK)* 21(JTAG_TDO)* 22(JTAG_TMS)* 23(JTAG_TDI)*

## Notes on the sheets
sheet 23
- BOARD ID EEPROM
- I2C ADDRESS: 0X51
- DIGITAL TEMPERATURE SENSORS
- I2C ADDRESS: 0x48
- I2C ADDRESS: 0x49
- CAD NOTE: PLACE TEMP SENSOR CLOSE TO SoC
- CAD NOTE: PLACE TEMP SENSOR CLOSE TO DDR4
- Silk: SOC_I2C1
sheet 24
- CPSW3G RGMII 1 - ETHERNET PHY
- D-Note :-
  The caps and values used are  as per the EPHY
  data sheet recommendations.
- D-Note :-
  Refer to DP83867ERGZ-R-EVM when
  using LAN Discrete Transformer
  Module and RJ45 connector
- R-Note :-
  Ferrite is DNI
- D-Note :-
  Verify the power sequence
  requirements for Two-Supply
  Configuration and Three-Supply
  Configuration
- RJ45 CONNECTOR WITH
  INTEGRATED MAGNETICS
- 100E
- 100E
- D-Note :-
  Provide provision for Series resistor
  based on EPHY for RX signals near to EPHY
- 100E
- 100E
- D-Note :-
  Refer EPHY EVM for JTAG connections
- Note :-
  Add a series resistor to the GPIO
  input for isolation or testing
  Refer SK-AM62P-LP schematics
- Note :-
  Pullup is enabled for GPIO input
  RESETSTATz series resistor is DNI
- Silk: RGMII-1
- D-Note
  Anding logic could be optimized to 2 input AND gate
  Use RESETSTATz (or PORz_OUT) and the SoC IO as inputs
- D-Note :-
  ANDing logic additionally performs level translation
  Verify the Reset IO level compatibility before
  optimizing the reset ANDing logic.
  IO level mismatch could cause supply leakage and
  affect SOC operation
- PHY ADDRESS = 0000
- Auto-negotiation Disabled
- 10/100/1000 advertised, Auto-MDI-X
- Tx Clock Skew = 0ns
- Rx Clock Skew = 2ns
sheet 25
- SOC MAC INTERFACE
- CLOCK BUFFER FOR SOC AND ETHERNET PHYs
- D-Note :-
  Add an additional bulk cap
- D-Note:-
  C and R must be DNI.
  Mounting these components
  affects the  output clock
  amplitude and
  board performance.
- D-Note :-
  Add series resistors 22 R on the Ethernet
  interface TX (TDx) signals near to the SoC
